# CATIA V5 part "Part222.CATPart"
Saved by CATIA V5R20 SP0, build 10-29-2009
Part number: DFA 168700-2 comprimido
Revision: ANY
Definition: UNKNOWN
Nomenclature: DFA 168700-2 comprimido
Source: Unknown
Bounding box of the stored display mesh (mm): x -2.8 to 2.8, y 0 to 4.04, z -2.8 to 2.8
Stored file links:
  C:\Users\Utente\Desktop\IO LAVORO\3D X SITO CF\CUMSA\3D files FA\FA 200710-21\Part222.CATPart

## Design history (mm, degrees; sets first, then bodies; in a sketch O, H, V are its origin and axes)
Body1 "Cortar-Extruir1" (main body)
  Solid1: solid without history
